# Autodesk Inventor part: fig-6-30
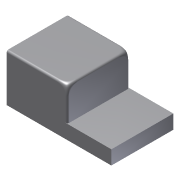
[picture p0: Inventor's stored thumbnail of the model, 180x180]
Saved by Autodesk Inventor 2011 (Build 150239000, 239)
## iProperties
Created: 2004-05
Part Number: fig-6-30
Document SubType Name: Modeling
Designer: CADCIM Technologies
Manufacturer: Standard
Standards Organization: Custom
Density: 1 g/cm^3
Author: CADCIM Technologies
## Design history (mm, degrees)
node "Sketch1"
sketch "Sketch2"
  geometry: L1 (0.098, 47.711)-(0.098, 0.049); L2 (0.098, 0.049)-(-105.483, 0.049); L3 (-105.483, 0.049)-(-105.483, 14.192); L4 (-105.483, 14.192)-(-61.139, 14.192); L5 (-61.139, 14.192)-(-61.139, 47.711); L6 (-61.139, 47.711)-(0.098, 47.711)
  constraints: 12 end point, 3 parallel, 2 perpendicular, 1 vertical
extrude "Extrusion1" new body sketch "Sketch2" stored distance "d0" = 62.5; taper "d1" = 0 deg
fillet "Fillet6" dims "d43" = 10, "d44" = 10, "d45" = 10, "d46" = 10, "d47" = 10, "d48" = 10, "d49" = 2
body "Solid1"
